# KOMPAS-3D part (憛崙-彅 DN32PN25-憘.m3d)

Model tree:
1. Объединить компоненты:1  (labels: СЕНС-ПФ DN32PN25)
2. Эскиз:1
3. Операция выдавливания:1
     Расстояние 1 = 14
4. Фаска:1
     Угол = 45; Длина 1 = 2; Длина 2 = 2

Referenced files in D:\Савин\!СЕНСОР\3D для заказчика\!Новый перечень\СЕНС-ПФ\DN32\: СЕНС-ПФ DN32PN25.a3d
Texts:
  СЕНС-ПФ DN32PN25-СВ
  ООО НПП Сенсор
  СЕНС-ПФ DN32PN25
